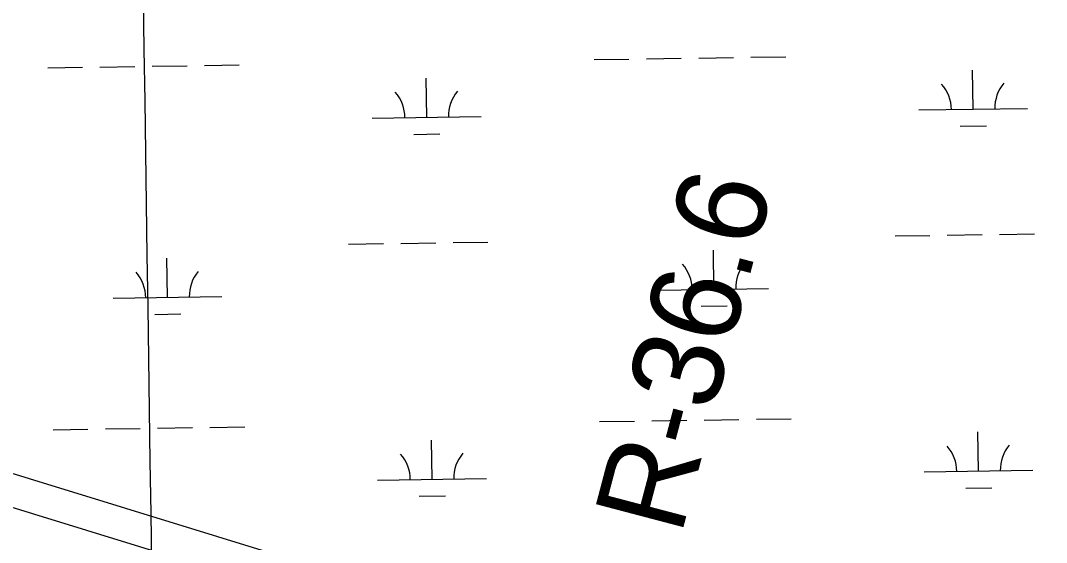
# Model space of a CAD drawing. Extents: x 3807117 to 3845308, y 337856 to 363736.
# Drawn here: x 3816388 to 3817330, y 354363 to 354843 of the extents above; entities that cross this region are included whole.
import ezdxf

# ---------------------------------------------------------------- set-up
doc = ezdxf.new("R2010")
doc.units = 0
for name, color, linetype in [('V-GRID-MAJR', 7, 'Continuous'), ('V-RIVR-RANG-IDEN', 7, 'Continuous'), ('V-ROAD-CNTR', 7, 'Continuous'), ('V-WETL-SWMP', 7, 'Continuous')]:
    doc.layers.add(name, color=color, linetype=linetype)

msp = doc.modelspace()

# ---------------------------------------------------------------- linework, layer by layer
at = {"layer": 'V-GRID-MAJR'}
msp.add_spline([(3816669.93, 343360.88), (3816580.93, 349419.09), (3816491.9, 355479.23), (3816402.87, 361539.38), (3816402.84, 361541.3)], degree=3, dxfattribs=at)
at = {"layer": 'V-ROAD-CNTR'}
for points in [[(3811176.91, 356806.71), (3811585.08, 356528.57), (3812098.27, 356204.16), (3813162.14, 355630.42), (3813949.57, 355328.51), (3815071.07, 354906.16), (3816218.55, 354476.67), (3817272.58, 354151.75), (3817573.42, 354062.42), (3818142.24, 353962.75), (3818819.76, 353880.03), (3819674.98, 353862.29)], [(3811160.02, 356781.92), (3811568.61, 356503.49), (3812083.12, 356178.25), (3813149.6, 355603.1), (3813938.92, 355300.46), (3815060.52, 354878.07), (3816208.87, 354448.26), (3817263.89, 354123.03), (3817566.54, 354033.17), (3818137.83, 353933.06), (3818817.63, 353850.07), (3819674.87, 353832.29)]]:
    msp.add_lwpolyline(points, dxfattribs=at)
at = {"layer": 'V-WETL-SWMP'}
for p, q in [((3817058.64, 354809.18), (3817090.63, 354809.66)), ((3816460.79, 354800.22), (3816492.79, 354800.7)), ((3816508.79, 354800.94), (3816540.79, 354801.42)), ((3816556.78, 354801.66), (3816588.78, 354802.14)), ((3816914.65, 354807.02), (3816946.65, 354807.5)), ((3816962.65, 354807.74), (3816994.64, 354808.22)), ((3817010.64, 354808.46), (3817042.64, 354808.94)), ((3816412.8, 354799.5), (3816444.8, 354799.98)), ((3817262.69, 354761.49), (3817262.15, 354797.48)), ((3816760.84, 354753.97), (3816760.3, 354789.96)), ((3816710.84, 354753.22), (3816810.83, 354754.72)), ((3817212.69, 354760.74), (3817312.68, 354762.24)), ((3817250.92, 354745.88), (3817274.92, 354746.24)), ((3816749.07, 354738.36), (3816773.07, 354738.72)), ((3817191.02, 354644.97), (3817223.01, 354645.45)), ((3817239.01, 354645.69), (3817271.01, 354646.17)), ((3817287.01, 354646.41), (3817319, 354646.89)), ((3816689.17, 354637.45), (3816721.16, 354637.93)), ((3816737.16, 354638.17), (3816769.16, 354638.65)), ((3816785.16, 354638.89), (3816817.15, 354639.37)), ((3817024.67, 354596.04), (3817024.13, 354632.04)), ((3816522.82, 354588.52), (3816522.28, 354624.52)), ((3816974.67, 354595.29), (3817074.66, 354596.79)), ((3816472.82, 354587.77), (3816572.81, 354589.27)), ((3817012.9, 354580.43), (3817036.9, 354580.79)), ((3816511.05, 354572.91), (3816535.05, 354573.27)), ((3816919.64, 354474.38), (3816951.63, 354474.86)), ((3816967.63, 354475.1), (3816999.63, 354475.58)), ((3817015.62, 354475.82), (3817047.62, 354476.3)), ((3817063.62, 354476.54), (3817095.62, 354477.02)), ((3816417.78, 354466.86), (3816449.78, 354467.34)), ((3816465.78, 354467.58), (3816497.77, 354468.06)), ((3816513.77, 354468.3), (3816545.77, 354468.78)), ((3816561.77, 354469.02), (3816593.76, 354469.5)), ((3817267.67, 354428.85), (3817267.13, 354464.84)), ((3816765.82, 354421.33), (3816765.28, 354457.33)), ((3817217.68, 354428.1), (3817317.67, 354429.6)), ((3816715.83, 354420.58), (3816815.81, 354422.08)), ((3816754.05, 354405.72), (3816778.05, 354406.08)), ((3817255.9, 354413.24), (3817279.9, 354413.6))]:
    msp.add_line(p, q, dxfattribs=at)
for centre, start, end in [((3817207.44, 354761.13), 0.08653, 41.63019), ((3817317.92, 354762.79), 140.08653, 181.63019), ((3816705.59, 354753.61), 0.08653, 41.63019), ((3816816.07, 354755.27), 140.08653, 181.63019), ((3816578.05, 354589.82), 140.08653, 181.63019), ((3816969.42, 354595.69), 0.08653, 41.63019), ((3817079.9, 354597.34), 140.08653, 181.63019), ((3816467.57, 354588.17), 0.08653, 41.63019), ((3817212.43, 354428.5), 0.08653, 41.63019), ((3817322.9, 354430.15), 140.08653, 181.63019), ((3816710.58, 354420.98), 0.08653, 41.63019), ((3816821.05, 354422.63), 140.08653, 181.63019)]:
    msp.add_arc(centre, 35.25, start, end, dxfattribs=at)

# ---------------------------------------------------------------- texts
at = {"layer": 'V-RIVR-RANG-IDEN'}
msp.add_text('R-36.6', height=83, rotation=75.23685, dxfattribs=at).set_placement((3816994.32, 354368.5))

doc.saveas('drawing.dxf')
